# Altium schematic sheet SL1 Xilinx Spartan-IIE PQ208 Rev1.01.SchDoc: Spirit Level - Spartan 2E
size A3; Organization: Altium Limited; Address1: L3, 12a Rodborough Rd; Address2: Frenchs Forest; Address3: NSW; Address4: Australia 2086; DocumentNumber: 5; SheetNumber: 5; SheetTotal: 5
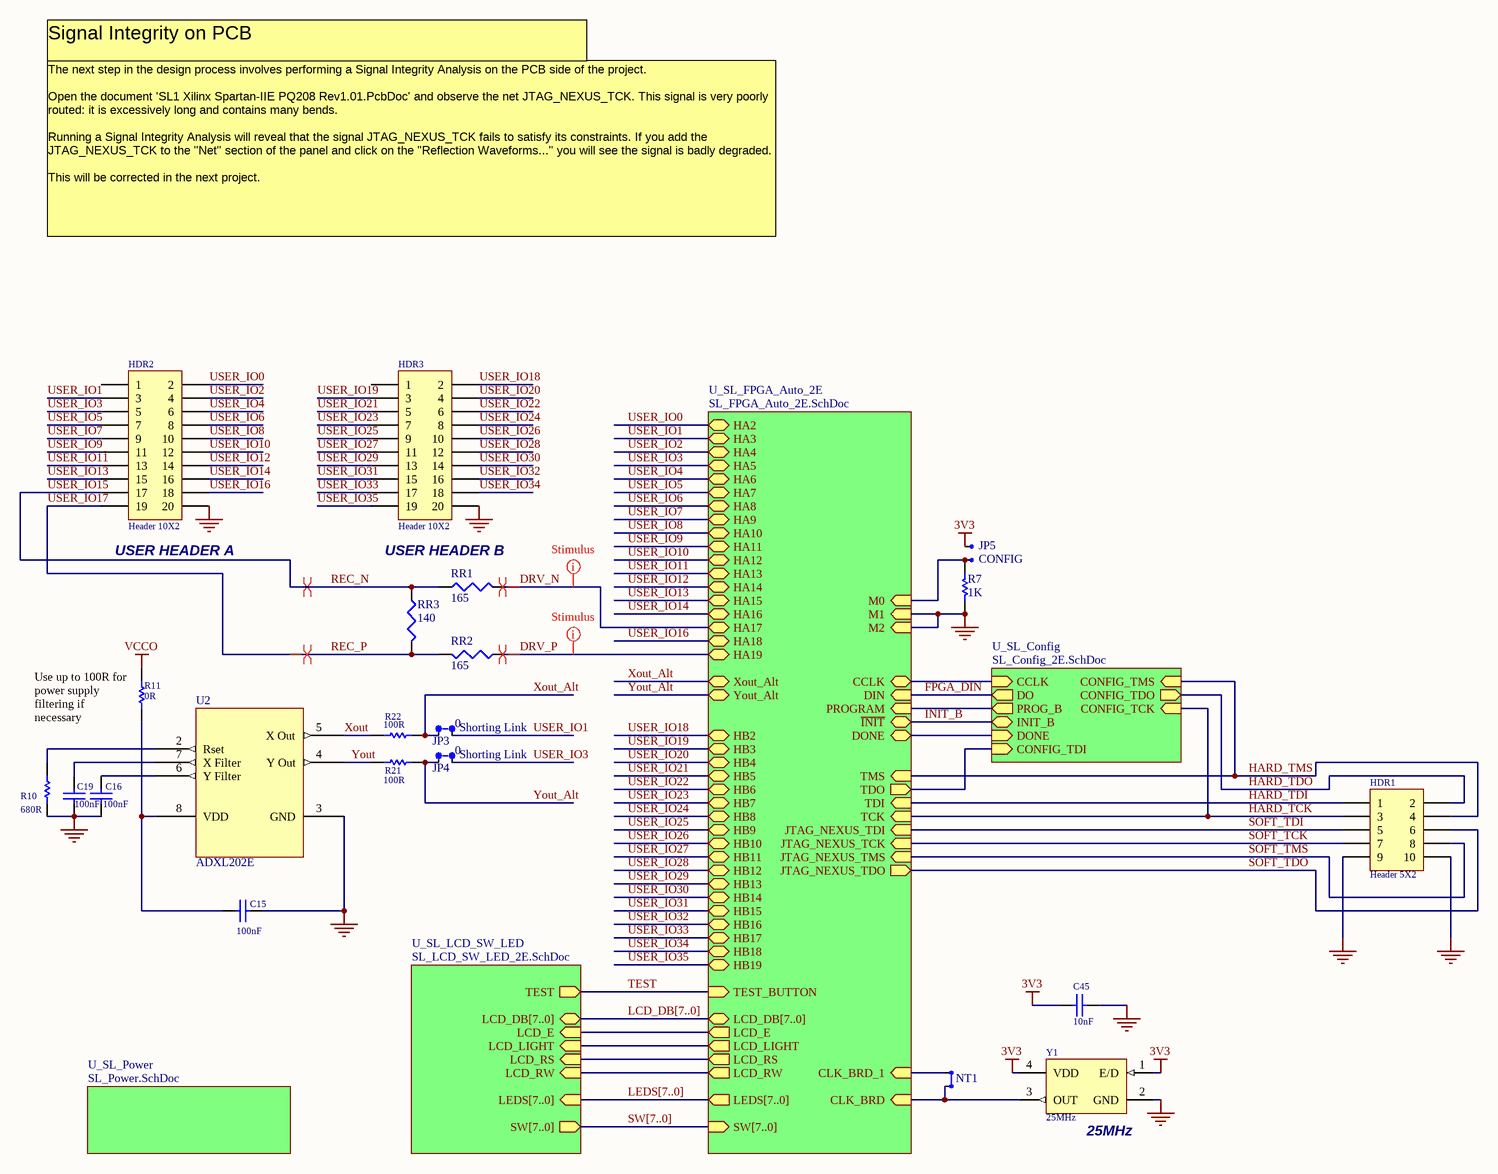
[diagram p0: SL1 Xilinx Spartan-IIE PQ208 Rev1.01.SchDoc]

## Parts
C15  100nF  [CC1608-0603]
C16  100nF  [CC1608-0603]
C19  100nF  [CC1608-0603]
C45  10nF  [CC1608-0603]
HDR1  Header 5X2  [HDR2X5_LP]
HDR2  Header 10X2  [HDR2X10]
HDR3  Header 10X2  [HDR2X10]
JP3  X axis  [HDR1X2]  (value not drawn)
JP4  Y axis  [HDR1X2]  (value not drawn)
JP5  CONFIG  [HDR1X2]
JS2  Shorting Link  value 0  (mechanical)
JS3  Shorting Link  value 0  (mechanical)
NT1  *  [NT]  (value not drawn)  (net tie, no BOM)
R7  1K  [CR2012-0805]
R10  680R  [CR2012-0805]
R11  0R  [CR2012-0805]
R21  100R  [CR2012-0805]
R22  100R  [CR2012-0805]
RR1  value 165  [AXIAL-0.3]  (hidden comment: Comment)
RR2  value 165  [AXIAL-0.3]  (hidden comment: Comment)
RR3  value 140  [AXIAL-0.3]  (hidden comment: Comment)
U2  ADXL202E  [E-8]
Y1  25MHz  [QSMO_4200]

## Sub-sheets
U_SL_Config = SL_Config_2E.SchDoc: PROG_B (out), CONFIG_TDO (out), DO (out), CCLK (in), CONFIG_TDI (in), CONFIG_TCK (in), CONFIG_TMS (in), INIT_B (bidir), DONE (in)
U_SL_FPGA_Auto_2E = SL_FPGA_Auto_2E.SchDoc: CLK_BRD (in), HA10 (bidir), HA11 (bidir), HA12 (bidir), HA13 (bidir), HA14 (bidir), HA15 (bidir), HA16 (bidir), HA17 (bidir), HA18 (bidir), HA19 (bidir), HA2 (bidir), HA3 (bidir), HA4 (bidir), HA5 (bidir), HA6 (bidir), HA7 (bidir), HA8 (bidir), HA9 (bidir), HB10 (bidir), HB11 (bidir), HB12 (bidir), HB13 (bidir), HB14 (bidir), HB15 (bidir), HB16 (bidir), HB17 (bidir), HB18 (bidir), HB19 (bidir), HB2 (bidir), HB3 (bidir), HB4 (bidir), HB5 (bidir), HB6 (bidir), HB7 (bidir), HB8 (bidir), HB9 (bidir), JTAG_NEXUS_TCK (in), JTAG_NEXUS_TDI (in), JTAG_NEXUS_TDO (out), JTAG_NEXUS_TMS (in), LCD_DB[7..0] (bidir), LCD_E (out), LCD_LIGHT (out), LCD_RS (out), LCD_RW (out), LEDS[7..0] (out), SW[7..0] (in), TEST_BUTTON (in), CCLK (bidir), DONE (bidir), M0 (in), M1 (in), M2 (in), PROGRAM (in), TCK (in), TDI (in), TDO (out), TMS (in), DIN (in), ~{INIT} (bidir), CLK_BRD_1 (in), Xout_Alt, Yout_Alt
U_SL_LCD_SW_LED = SL_LCD_SW_LED_2E.SchDoc: TEST (out), SW[7..0] (out), LCD_DB[7..0] (bidir), LCD_E (in), LCD_RS (in), LCD_RW (in), LCD_LIGHT (in), LEDS[7..0] (in)
U_SL_Power = SL_Power.SchDoc: no entries

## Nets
3V3: C45.1 JP5.2 Y1.1(E/D) Y1.4(VDD)
GND: C15.2 C16.2 C19.2 C45.2 HDR1.9 HDR1.10 HDR2.20 HDR3.20 R7.1 R10.1 U2.3(GND) Y1.2(GND) ; sheet U_SL_FPGA_Auto_2E/M1, sheet U_SL_FPGA_Auto_2E/M2
VCCO: R11.1
DRV_N: RR1.1 ; sheet U_SL_FPGA_Auto_2E/HA17
DRV_P: RR2.2 ; sheet U_SL_FPGA_Auto_2E/HA19
FPGA_DIN: sheet U_SL_Config/DO, sheet U_SL_FPGA_Auto_2E/DIN
HARD_TCK: HDR1.3 ; sheet U_SL_Config/CONFIG_TCK, sheet U_SL_FPGA_Auto_2E/TCK
HARD_TDI: HDR1.1 ; sheet U_SL_FPGA_Auto_2E/TDI
HARD_TDO: HDR1.2 ; sheet U_SL_Config/CONFIG_TDO
HARD_TMS: HDR1.4 ; sheet U_SL_Config/CONFIG_TMS, sheet U_SL_FPGA_Auto_2E/TMS
INIT_B: sheet U_SL_Config/INIT_B, sheet U_SL_FPGA_Auto_2E/~{INIT}
REC_N: HDR2.17 RR1.2 RR3.2  [also labelled USER_IO15]
REC_P: HDR2.19 RR2.1 RR3.1  [also labelled USER_IO17]
SOFT_TCK: HDR1.7 ; sheet U_SL_FPGA_Auto_2E/JTAG_NEXUS_TCK
SOFT_TDI: HDR1.5 ; sheet U_SL_FPGA_Auto_2E/JTAG_NEXUS_TDI
SOFT_TDO: HDR1.6 ; sheet U_SL_FPGA_Auto_2E/JTAG_NEXUS_TDO
SOFT_TMS: HDR1.8 ; sheet U_SL_FPGA_Auto_2E/JTAG_NEXUS_TMS
TEST: sheet U_SL_LCD_SW_LED/TEST, sheet U_SL_FPGA_Auto_2E/TEST_BUTTON
USER_IO0: HDR2.2 ; sheet U_SL_FPGA_Auto_2E/HA2
USER_IO1: HDR2.3 JP3.2 ; sheet U_SL_FPGA_Auto_2E/HA3
USER_IO2: HDR2.4 ; sheet U_SL_FPGA_Auto_2E/HA4
USER_IO3: HDR2.5 JP4.2 ; sheet U_SL_FPGA_Auto_2E/HA5
USER_IO4: HDR2.6 ; sheet U_SL_FPGA_Auto_2E/HA6
USER_IO5: HDR2.7 ; sheet U_SL_FPGA_Auto_2E/HA7
USER_IO6: HDR2.8 ; sheet U_SL_FPGA_Auto_2E/HA8
USER_IO7: HDR2.9 ; sheet U_SL_FPGA_Auto_2E/HA9
USER_IO8: HDR2.10 ; sheet U_SL_FPGA_Auto_2E/HA10
USER_IO9: HDR2.11 ; sheet U_SL_FPGA_Auto_2E/HA11
USER_IO10: HDR2.12 ; sheet U_SL_FPGA_Auto_2E/HA12
USER_IO11: HDR2.13 ; sheet U_SL_FPGA_Auto_2E/HA13
USER_IO12: HDR2.14 ; sheet U_SL_FPGA_Auto_2E/HA14
USER_IO13: HDR2.15 ; sheet U_SL_FPGA_Auto_2E/HA15
USER_IO14: HDR2.16 ; sheet U_SL_FPGA_Auto_2E/HA16
USER_IO16: HDR2.18 ; sheet U_SL_FPGA_Auto_2E/HA18
USER_IO18: HDR3.2 ; sheet U_SL_FPGA_Auto_2E/HB2
USER_IO19: HDR3.3 ; sheet U_SL_FPGA_Auto_2E/HB3
USER_IO20: HDR3.4 ; sheet U_SL_FPGA_Auto_2E/HB4
USER_IO21: HDR3.5 ; sheet U_SL_FPGA_Auto_2E/HB5
USER_IO22: HDR3.6 ; sheet U_SL_FPGA_Auto_2E/HB6
USER_IO23: HDR3.7 ; sheet U_SL_FPGA_Auto_2E/HB7
USER_IO24: HDR3.8 ; sheet U_SL_FPGA_Auto_2E/HB8
USER_IO25: HDR3.9 ; sheet U_SL_FPGA_Auto_2E/HB9
USER_IO26: HDR3.10 ; sheet U_SL_FPGA_Auto_2E/HB10
USER_IO27: HDR3.11 ; sheet U_SL_FPGA_Auto_2E/HB11
USER_IO28: HDR3.12 ; sheet U_SL_FPGA_Auto_2E/HB12
USER_IO29: HDR3.13 ; sheet U_SL_FPGA_Auto_2E/HB13
USER_IO30: HDR3.14 ; sheet U_SL_FPGA_Auto_2E/HB14
USER_IO31: HDR3.15 ; sheet U_SL_FPGA_Auto_2E/HB15
USER_IO32: HDR3.16 ; sheet U_SL_FPGA_Auto_2E/HB16
USER_IO33: HDR3.17 ; sheet U_SL_FPGA_Auto_2E/HB17
USER_IO34: HDR3.18 ; sheet U_SL_FPGA_Auto_2E/HB18
USER_IO35: HDR3.19 ; sheet U_SL_FPGA_Auto_2E/HB19
Xout: R22.2 U2.5(X_Out)
Xout_Alt: JP3.1 R22.1 ; sheet U_SL_FPGA_Auto_2E/Xout_Alt
Yout: R21.2 U2.4(Y_Out)
Yout_Alt: JP4.1 R21.1 ; sheet U_SL_FPGA_Auto_2E/Yout_Alt
NetC15_1: C15.1 R11.2 U2.8(VDD)
NetC16_1: C16.1 U2.6(Y_Filter)
NetC19_1: C19.1 U2.7(X_Filter)
NetJP5_1: JP5.1 R7.2 ; sheet U_SL_FPGA_Auto_2E/M0
NetNT1_1: NT1.1 ; sheet U_SL_FPGA_Auto_2E/CLK_BRD_1
NetNT1_2: NT1.2 Y1.3(OUT) ; sheet U_SL_FPGA_Auto_2E/CLK_BRD
NetR10_2: R10.2 U2.2(Rset)
(unnamed): sheet U_SL_Config/PROG_B, sheet U_SL_FPGA_Auto_2E/PROGRAM
(unnamed): sheet U_SL_Config/CCLK, sheet U_SL_FPGA_Auto_2E/CCLK  [a separate net that carries the same name]
(unnamed): sheet U_SL_Config/CONFIG_TDI, sheet U_SL_FPGA_Auto_2E/TDO  [a separate net that carries the same name]
(unnamed): sheet U_SL_Config/DONE, sheet U_SL_FPGA_Auto_2E/DONE  [a separate net that carries the same name]
(unnamed): sheet U_SL_LCD_SW_LED/LCD_E, sheet U_SL_FPGA_Auto_2E/LCD_E  [a separate net that carries the same name]
(unnamed): sheet U_SL_LCD_SW_LED/LCD_RS, sheet U_SL_FPGA_Auto_2E/LCD_RS  [a separate net that carries the same name]
(unnamed): sheet U_SL_LCD_SW_LED/LCD_RW, sheet U_SL_FPGA_Auto_2E/LCD_RW  [a separate net that carries the same name]
(unnamed): sheet U_SL_LCD_SW_LED/LCD_LIGHT, sheet U_SL_FPGA_Auto_2E/LCD_LIGHT  [a separate net that carries the same name]

Not connected (* = marked no-connect by the designer): HDR2 1; HDR3 1; U2 1(Self_Test)

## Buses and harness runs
bus LCD_DB[7..0] = sheet U_SL_FPGA_Auto_2E/LCD_DB[7..0] = sheet U_SL_LCD_SW_LED/LCD_DB[7..0]
bus LEDS[7..0] = sheet U_SL_FPGA_Auto_2E/LEDS[7..0] = sheet U_SL_LCD_SW_LED/LEDS[7..0]
bus SW[7..0] = sheet U_SL_FPGA_Auto_2E/SW[7..0] = sheet U_SL_LCD_SW_LED/SW[7..0]

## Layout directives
differential pair: DRV_N, DRV_P, REC_N, REC_P
rule Signal Stimulus [Kind - Single Pulse    Level - High    Start Time = 10.00n    Stop Time = 60.00n    Period Time = 100.0n]: DRV_N
rule Signal Stimulus [Kind - Single Pulse    Level - Low    Start Time = 10.00n    Stop Time = 60.00n    Period Time = 100.0n]: DRV_P

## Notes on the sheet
- Signal Integrity on PCB
- The next step in the design process involves performing a Signal Integrity Analysis on the PCB side of the project.
  Open the document 'SL1 Xilinx Spartan-IIE PQ208 Rev1.01.PcbDoc' and observe the net JTAG_NEXUS_TCK. This signal is very poorly routed: it is excessively long and contains many bends.
  Running a Signal Integrity Analysis will reveal that the signal JTAG_NEXUS_TCK fails to satisfy its constraints. If you add the JTAG_NEXUS_TCK to the "Net" section of the panel and click on the "Reflection Waveforms..." you will see the signal is badly degraded.
  This will be corrected in the next project.
- (near HDR2) USER HEADER A
- USER HEADER B
- (near R11) Use up to 100R for power supply filtering if necessary
- (near Y1) 25MHz

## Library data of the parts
C15 C16 C19 = CAP: Capacitor; AEMS Code: 2101550
C45 = CAP: Capacitor; AEMS Code: 2100341
HDR1 = Header 5X2: Header, 5-Pin, Dual row
HDR2 HDR3 = Header 10X2: Header, 10-Pin, Dual row
JP3-JP5 NT1 = Jumper, 2-Pin
JS2 JS3 = Jumper Socket: Shorting Link, 2.54mm (0.1") Pitch
R7 = RES: Resistor; AEMS Code: 1200008JN
R10 = Res1: Resistor; AEMS Code: CHANGED VALUE
R11 = RES: Resistor; AEMS Code: 1200075
R21 R22 = Res1: Resistor; AEMS Code: 1200012JT
RR1-RR3 = Res3: Resistor
U2 = ADXL202E: Accelerometer with Digital Output
Y1 = QSMO_4200: Surface Mount Crystal Oscillator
